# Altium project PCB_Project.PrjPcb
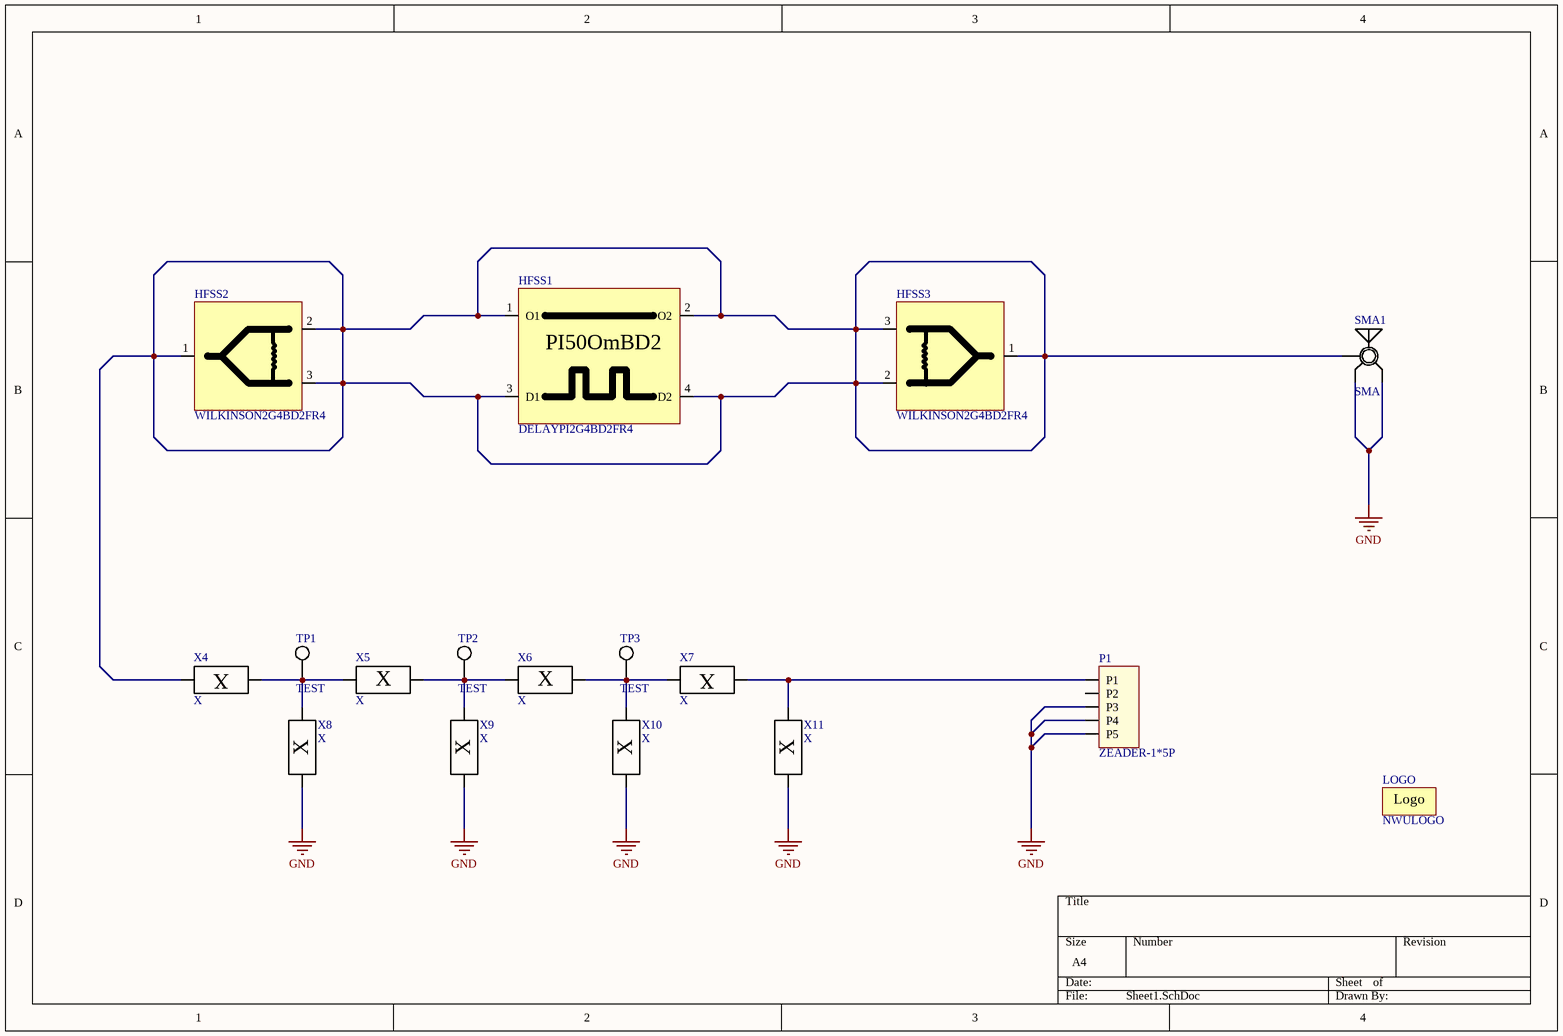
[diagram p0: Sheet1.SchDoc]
1 sheet, 17 parts. Net scope: global (net labels, ports and power ports of the same name join across sheets).
Board file: wilkinson2G4.PcbDoc

## Sheet Sheet1.SchDoc
size A4; SheetNumber: 1; SheetTotal: 1

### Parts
HFSS1  DELAYPI2G4BD2FR4  [DELAYPI2G4BD2FR4]
HFSS2  WILKINSON2G4BD2FR4  [WILKINSON2G4BD2FR4]
HFSS3  WILKINSON2G4BD2FR4  [WILKINSON2G4BD2FR4]
LOGO  NWULOGO  [NorthwestLogo]
P1  ZEADER-1*5P  [HDR2.54-LI-5P]
SMA1  SMA  [SMA-FR2]
TP1  TEST  [HFSS]
TP2  TEST  [HFSS]
TP3  TEST  [HFSS]
X4  X  [X0805]
X5  X  [X0805]
X6  X  [X0805]
X7  X  [X0805]
X8  X  [X0805]
X9  X  [X0805]
X10  X  [X0805]
X11  X  [X0805]

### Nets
GND: P1.3(P3) P1.4(P4) P1.5(P5) SMA1.2(GND) SMA1.3(GND) X8.1 X9.1 X10.1 X11.1
NetHFSS1_1: HFSS1.1(O1) HFSS1.2(O2) HFSS1.3(D1) HFSS1.4(D2) HFSS2.1 HFSS2.2 HFSS2.3 HFSS3.1 HFSS3.2 HFSS3.3 SMA1.1(ANT) X4.2
NetP1_1: P1.1(P1) X7.1 X11.2
NetTP1_1: TP1.1 X4.1 X5.1 X8.2
NetTP2_1: TP2.1 X5.2 X6.1 X9.2
NetTP3_1: TP3.1 X6.2 X7.2 X10.2

Not connected (* = marked no-connect by the designer): P1 2(P2)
